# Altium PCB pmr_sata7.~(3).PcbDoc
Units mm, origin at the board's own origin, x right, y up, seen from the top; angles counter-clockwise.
Board outline 160 x 99.92 mm, 2 copper layers (Top Layer, Bottom Layer); 11 components, 38 nets, 173 pads, 16 vias.
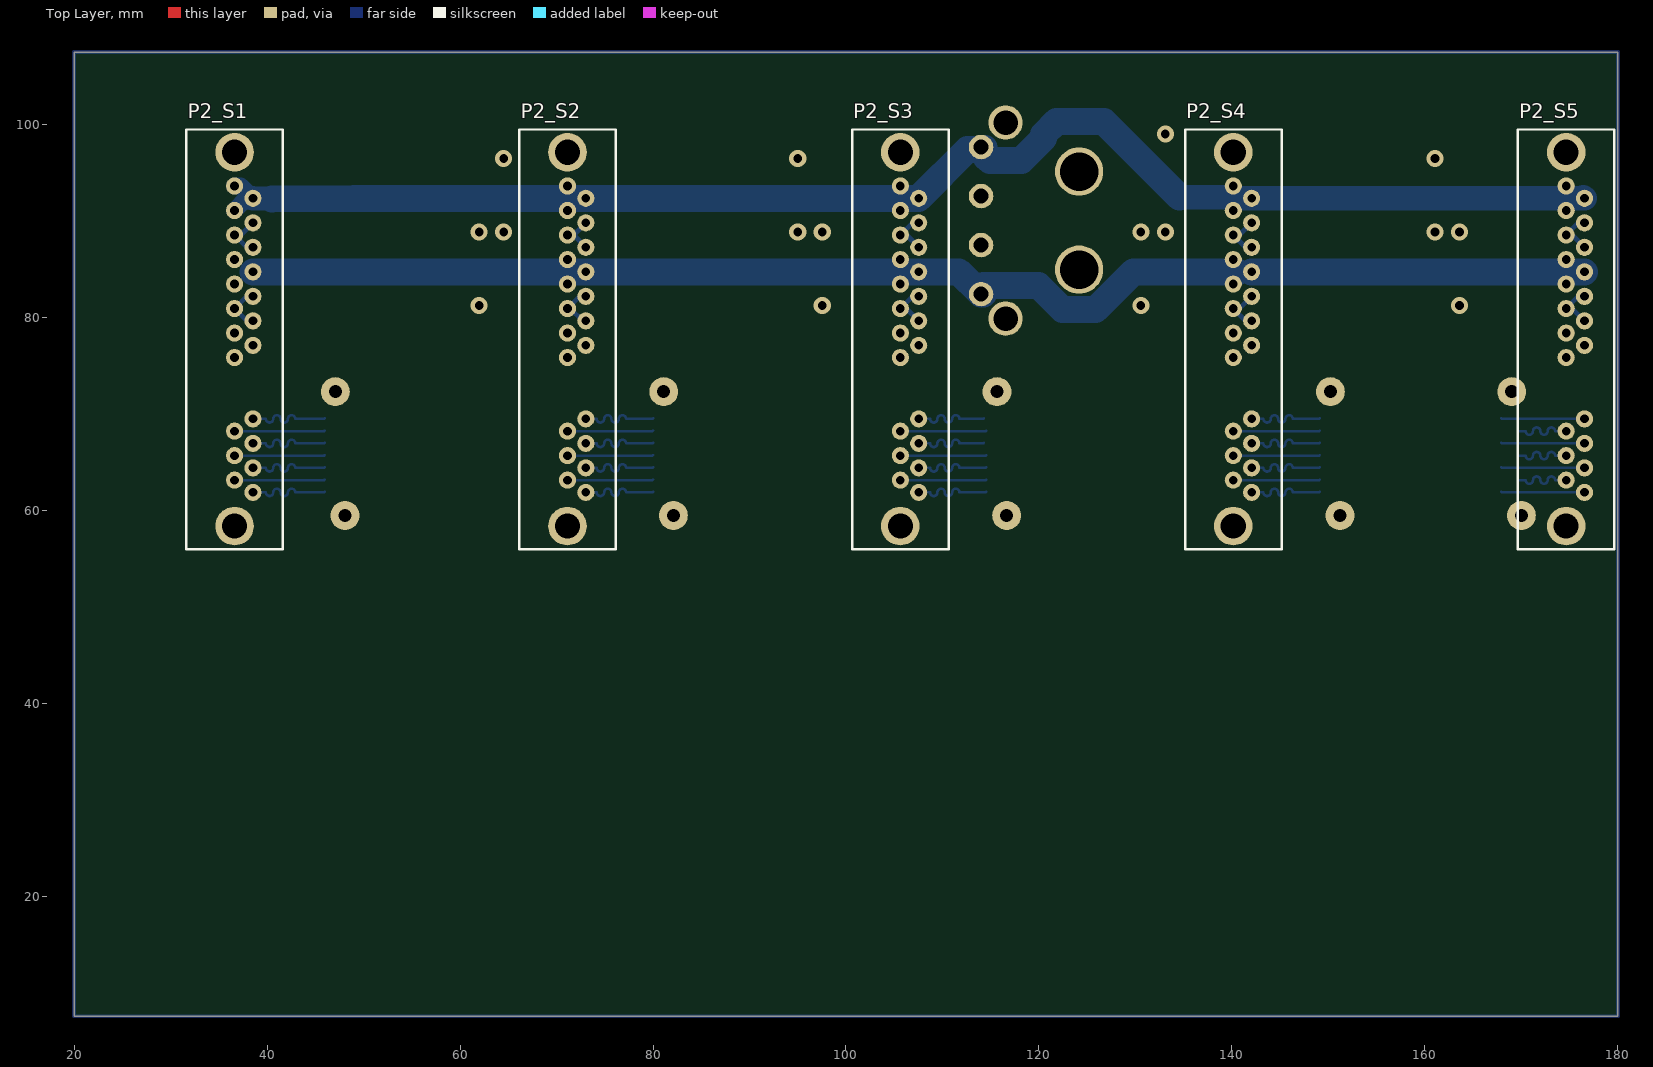
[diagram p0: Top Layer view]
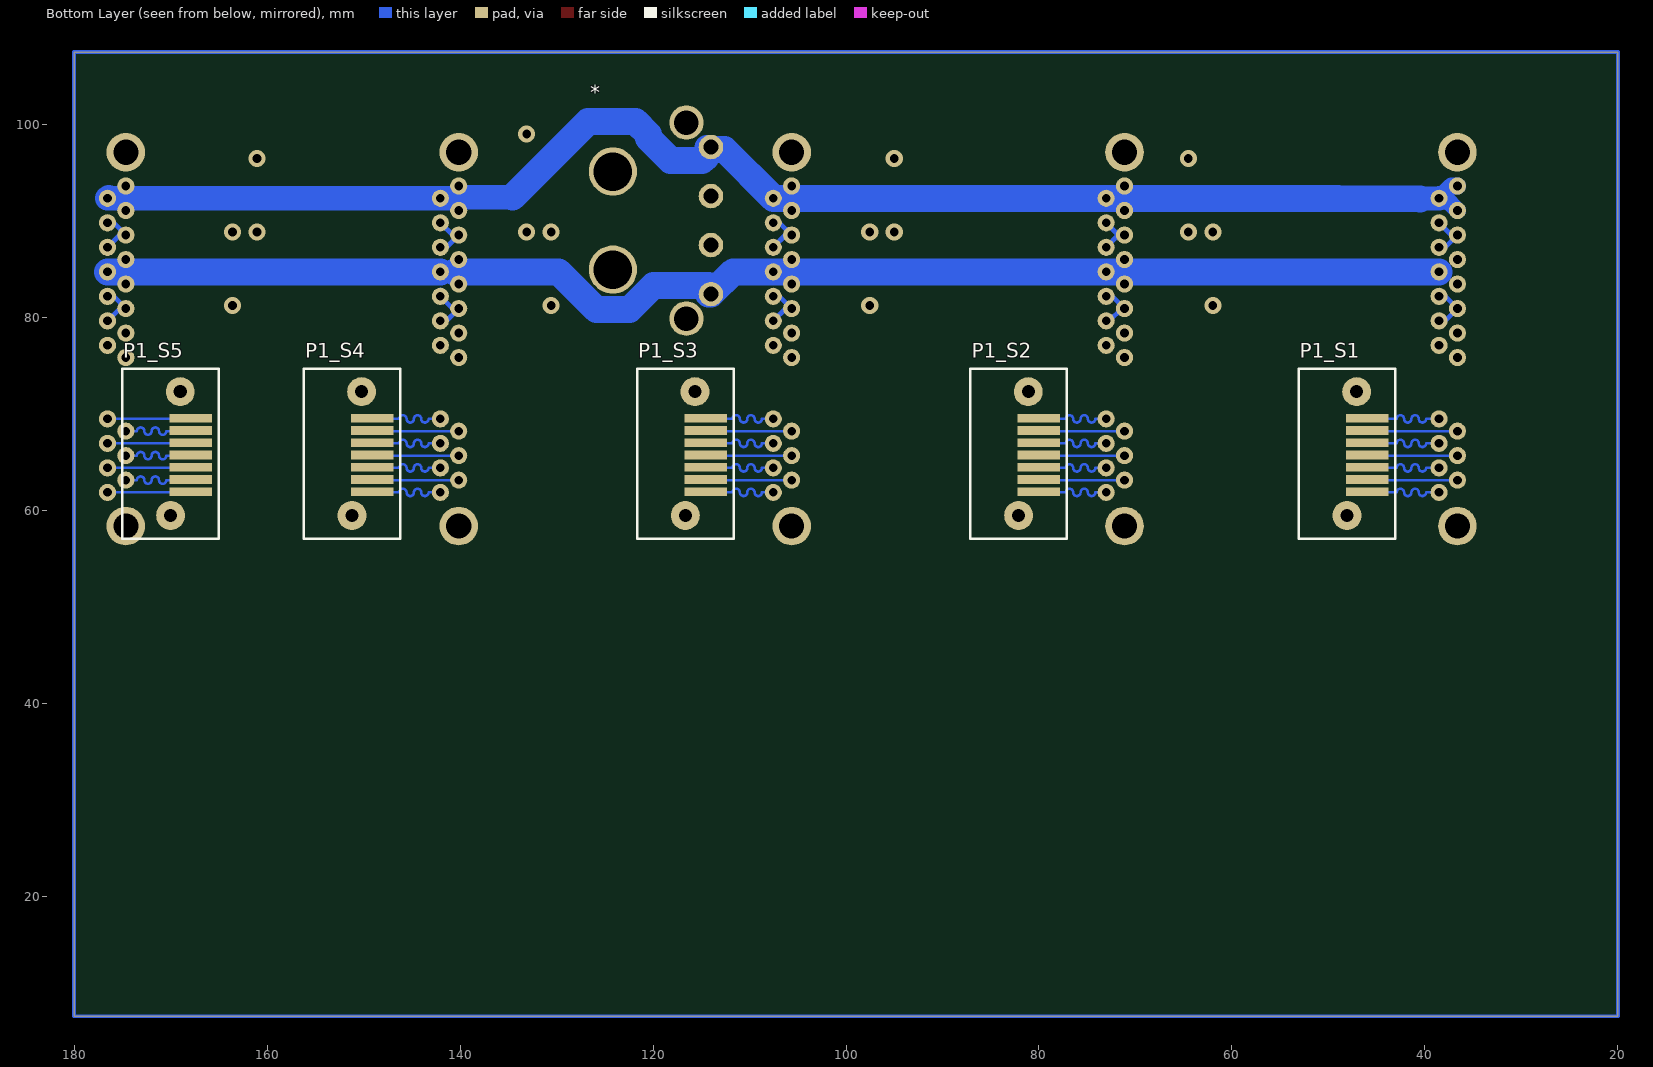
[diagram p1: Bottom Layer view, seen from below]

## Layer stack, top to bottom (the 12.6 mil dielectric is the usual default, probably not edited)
Top Solder: solder mask 0.0102, Solder Resist, Dk 3.5
Top Layer: signal copper 0.0356
Dielectric1: dielectric 0.32, FR-4, Dk 4.8
Bottom Layer: signal copper 0.0356
Bottom Solder: solder mask 0.0102, Solder Resist, Dk 3.5

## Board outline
20,7.62 20,107.544 180,107.544 180,7.62

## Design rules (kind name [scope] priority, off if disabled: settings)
Clearance [All] p1: gap=0.254
DiffPairsRouting [All] p1: maxlimit=0.254 minlimit=0.254 mostfreqgap=0.254 toplayer_minwidth=0.254 toplayer_maxwidth=0.381 toplayer_prefwidth=0.381 bottomlayer_minwidth=0.254 bottomlayer_maxwidth=0.381 bottomlayer_prefwidth=0.381 maxuncoupledlength=12.7
PolygonConnect [All] p1: connectstyle=Relief reliefconductorwidth=0.254 reliefentries=4 polygonreliefangle="90 Angle" airgapwidth=0.254
RoomDefinition top_level_sheet [InComponentClass('top_level_sheet')] p1 off: confinementstyle=ConfineIn formatcopy=TRUE lockcomponents=FALSE outline 180,10 197.5,10 197.5,37.5 180,37.5
RoomDefinition S5 [InComponentClass('S5')] p2 off: confinementstyle=ConfineIn formatcopy=TRUE lockcomponents=FALSE outline 29,122 53,122 53,170 29,170
RoomDefinition S3 [InComponentClass('S3')] p3 off: confinementstyle=ConfineIn formatcopy=TRUE lockcomponents=FALSE outline 76,114.83 100,114.83 100,162.83 76,162.83
RoomDefinition S2 [InComponentClass('S2')] p4 off: confinementstyle=ConfineIn formatcopy=TRUE lockcomponents=FALSE outline 108,115 132,115 132,163 108,163
RoomDefinition S1 [InComponentClass('S1')] p5 off: confinementstyle=ConfineIn formatcopy=TRUE lockcomponents=FALSE outline 127,116 151,116 151,164 127,164
RoomDefinition S4 [InComponentClass('S4')] p6 off: confinementstyle=ConfineIn formatcopy=TRUE lockcomponents=FALSE outline 192.278,29.464 184.912,29.464 184.912,40.386 192.278,40.386
RoutingVias [All] p1: holewidth=0.711 width=1.27 viastyle="Through Hole" minholewidth=0.711 minwidth=1.27 maxholewidth=0.711 maxwidth=1.27
SilkToSolderMaskClearance SilkscreenOverComponentPads [IsPad] p1: minsilkscreentomaskgap=0.254 clearancetoexposedcopper=TRUE
SolderMaskExpansion [All] p1: expansion=0.102
Width [All] p1: maxlimit=12.7 minlimit=0.254 preferedwidth=0.254
28 further rules are at their usual default settings.

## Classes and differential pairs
component class S1: P1_S1 P2_S1
component class S2: P1_S2 P2_S2
component class S3: P1_S3 P2_S3
component class S4: P1_S4 P2_S4
component class S5: P1_S5 P2_S5
channel class pmr_sata_single: S1 S2 S3 S4 S5
differential pair PAIR1_S1: +PAIR1_S1_P -PAIR1_S1_N
differential pair PAIR1_S2: +PAIR1_S2_P -PAIR1_S2_N
differential pair PAIR1_S3: +PAIR1_S3_P -PAIR1_S3_N
differential pair PAIR1_S4: +PAIR1_S4_P -PAIR1_S4_N
differential pair PAIR1_S5: +PAIR1_S5_P -PAIR1_S5_N
differential pair PAIR2_S1: +PAIR2_S1_P -PAIR2_S1_N
differential pair PAIR2_S2: +PAIR2_S2_P -PAIR2_S2_N
differential pair PAIR2_S3: +PAIR2_S3_P -PAIR2_S3_N
differential pair PAIR2_S4: +PAIR2_S4_P -PAIR2_S4_N
differential pair PAIR2_S5: +PAIR2_S5_P -PAIR2_S5_N

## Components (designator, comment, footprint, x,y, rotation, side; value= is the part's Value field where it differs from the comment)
* "PC_PWR_MOLEX" PC_PWR_MOLEX 124.156,90.08 r90 bottom
P1_S1 "SATA lille" "PMR_SATA -LILLE NY" 48.074,59.516 r270 bottom (schematic designator P1)
P1_S2 "SATA lille" "PMR_SATA -LILLE NY" 82.11,59.516 r270 bottom (schematic designator P1)
P1_S3 "SATA lille" "PMR_SATA -LILLE NY" 116.654,59.516 r270 bottom (schematic designator P1)
P1_S4 "SATA lille" "PMR_SATA -LILLE NY" 151.198,59.516 r270 bottom (schematic designator P1)
P1_S5 "SATA lille" "PMR_SATA -LILLE NY" 169.994,59.516 r270 bottom (schematic designator P1)
P2_S1 "SATA STOR" pmr_sata 36.636,58.42 r90 top (schematic designator P2)
P2_S2 "SATA STOR" pmr_sata 71.136,58.42 r90 top (schematic designator P2)
P2_S3 "SATA STOR" pmr_sata 105.636,58.42 r90 top (schematic designator P2)
P2_S4 "SATA STOR" pmr_sata 140.136,58.42 r90 top (schematic designator P2)
P2_S5 "SATA STOR" pmr_sata 174.636,58.42 r90 top (schematic designator P2)

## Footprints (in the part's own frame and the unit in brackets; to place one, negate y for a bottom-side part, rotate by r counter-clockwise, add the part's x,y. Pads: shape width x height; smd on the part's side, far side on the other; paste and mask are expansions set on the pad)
PC_PWR_MOLEX [mil]
  round 100 hole 60: 1(300,-400) 2(100,-400) 3(-100,-400) 4(-300,-400)
  round 140 hole 100: 5(400,-300) 6(-400,-300)
  round 196.85 hole 157.48: 7(-200,0) 8(200,0)
pmr_sata [mm]
  round 1.778 hole 0.9: P1(17.46,0) P2(18.73,-1.9) P3(20,0) P4(21.27,-1.9) P5(22.54,0) P6(23.81,-1.9) P7(25.08,0) P8(26.35,-1.9) P9(27.62,0) P10(28.89,-1.9) P11(30.16,0) P12(31.43,-1.9) P13(32.7,0) P14(33.97,-1.9) P15(35.24,0) S1(3.49,-1.9) S2(4.76,0) S3(6.03,-1.9) S4(7.3,0) S5(8.57,-1.9) S6(9.84,0) S7(11.11,-1.9)
  round 4 hole 2.6: S8(0,0) S8(38.74,0)
  silkscreen extent -2.4,-5 41.1,5
"PMR_SATA -LILLE NY" [mm]
  rect 0.9x4.4 smd: S1(-2.46,2.1) S2(-3.73,2.1) S3(-5,2.1) S4(-6.27,2.1) S5(-7.54,2.1) S6(-8.81,2.1) S7(-10.08,2.1)
  round 3 hole 1.35: S8(-12.83,1) S8(0,0)
  silkscreen extent -15.2,-5 2.4,5

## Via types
v1: diameter 1.778, hole 0.9, Top Layer to Bottom Layer, 16 vias

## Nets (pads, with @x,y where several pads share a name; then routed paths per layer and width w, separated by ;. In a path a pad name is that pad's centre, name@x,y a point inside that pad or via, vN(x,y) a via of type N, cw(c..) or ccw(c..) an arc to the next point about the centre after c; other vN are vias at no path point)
5V: *.4 P2_S1.P7 P2_S1.P8 P2_S1.P9 P2_S2.P7 P2_S2.P8 P2_S2.P9 P2_S3.P7 P2_S3.P8 P2_S3.P9 P2_S4.P7 P2_S4.P8 P2_S4.P9 P2_S5.P7 P2_S5.P8 P2_S5.P9 | length 141
  Bottom Layer w2.794: P2_S1.P8 P2_S2.P8 P2_S3.P8 111.686,84.77 *.4 114.227,82.46 114.227,83.349 119.937,83.349 122.437,80.849 125.875,80.849 129.796,84.77 140.556,84.77 ; P2_S4.P8 P2_S5.P8
12V: *.1 P2_S1.P13 P2_S1.P14 P2_S1.P15 P2_S2.P13 P2_S2.P14 P2_S2.P15 P2_S3.P13 P2_S3.P14 P2_S3.P15 P2_S4.P13 P2_S4.P14 P2_S4.P15 P2_S5.P13 P2_S5.P14 P2_S5.P15 | length 150.8
  Bottom Layer w1.778: P2_S1.P13 P2_S1.P14@37.906,92.39 ; P2_S1.P15 37.266,93.66 P2_S1.P14
  Bottom Layer w2.54: P2_S1.P14 40.513,92.329 ; *.1@113.752,97.456 *.1 114.406,97.7 *.1@114.406,96.52 ; 134.576,92.5 140.556,92.5 140.666,92.39 P2_S4.P14 P2_S5.P14 P2_S5.P14@176.426,92.5
  Bottom Layer w2.794: 40.513,92.329 49.022,92.373 65.532,92.373 65.549,92.39 P2_S2.P14 74.088,92.39 74.105,92.373 88.646,92.373 88.663,92.39 P2_S3.P14 112.602,97.456 *.1@113.752,97.456 ; 114.688,96.52 114.905,96.303 118.167,96.303 120.473,98.609 120.473,99.01 121.793,100.33 126.746,100.33 134.576,92.5
GND: P2_S1.P4 P2_S1.P5 P2_S1.P6 P2_S1.P10 P2_S1.P11 P2_S1.P12 P2_S2.P4 P2_S2.P5 P2_S2.P6 P2_S2.P10 P2_S2.P11 P2_S2.P12 P2_S3.P4 P2_S3.P5 P2_S3.P6 P2_S3.P10 P2_S3.P11 P2_S3.P12 P2_S4.P4 P2_S4.P5 P2_S4.P6 P2_S4.P10 P2_S4.P11 P2_S4.P12 P2_S5.P4 P2_S5.P5 P2_S5.P6 P2_S5.P10 P2_S5.P11 P2_S5.P12 | length 49.2
  Bottom Layer w0.508: P2_S1.P4 37.906,79.69 P2_S1.P5 37.906,82.23 P2_S1.P6 ; P2_S1.P10 37.906,87.31 P2_S1.P11 37.266,88.58 P2_S1.P12 ; P2_S2.P11 P2_S2.P11@71.766,88.58 ; P2_S2.P4 72.71,79.69 71.44,80.96 P2_S2.P5 72.406,82.23 P2_S2.P6 ; P2_S2.P10@73.036,86.675 P2_S2.P10 P2_S2.P11@71.766,88.58 ; P2_S2.P12 P2_S2.P11@71.766,88.58 ; P2_S3.P4 106.266,80.96 P2_S3.P5 106.906,82.23 P2_S3.P6 ; P2_S3.P10 106.266,88.58 P2_S3.P11 106.906,89.85 P2_S3.P12 ; P2_S4.P4 141.406,79.69 P2_S4.P5 140.766,80.96 P2_S4.P6 P2_S4.P6@142.036,82.865 ; P2_S4.P10 141.406,87.31 P2_S4.P11 140.766,88.58 P2_S4.P12 ; P2_S5.P4 175.266,80.96 P2_S5.P5 175.906,82.23 P2_S5.P6 ; P2_S5.P10 175.266,88.58 P2_S5.P11 175.906,89.85 P2_S5.P12
  other v1: 61.976,81.28 97.536,81.28 130.556,81.28 163.576,81.28 61.976,88.9 64.516,88.9 94.996,88.9 97.536,88.9 130.556,88.9 133.096,88.9 161.036,88.9 163.576,88.9 64.516,96.52 94.996,96.52 161.036,96.52 133.096,99.06
NetP1_S1_S1: P1_S1.S1 P2_S1.S1 | length 8.6
  Bottom Layer w0.254: P2_S1.S1@39.116,61.91 39.878,61.91 ccw(c40.259,61.91) 40.64,61.91 cw(c41.021,61.91) 41.402,61.91 ccw(c41.783,61.91) 42.164,61.91 cw(c42.545,61.91) 42.926,61.91 45.908,61.91 P1_S1.S1
NetP1_S1_S4: P1_S1.S4 P2_S1.S4 | length 9.4
  Bottom Layer w0.254: P2_S1.S4 45.908,65.72 P1_S1.S4
NetP1_S1_S7: P1_S1.S7 P2_S1.S7 | length 9.2
  Bottom Layer w0.254: P2_S1.S7 39.878,69.53 ccw(c40.259,69.53) 40.64,69.53 cw(c41.021,69.53) 41.402,69.53 ccw(c41.783,69.53) 42.164,69.53 cw(c42.545,69.53) 42.926,69.53 45.908,69.53 P1_S1.S7
NetP1_S2_S1: P1_S2.S1 P2_S2.S1 | length 8.4
  Bottom Layer w0.254: P2_S2.S1@73.406,61.91 74.168,61.91 ccw(c74.549,61.91) 74.93,61.91 cw(c75.311,61.91) 75.692,61.91 ccw(c76.073,61.91) 76.454,61.91 cw(c76.835,61.91) 77.216,61.91 79.944,61.91 P1_S2.S1
NetP1_S2_S4: P1_S2.S4 P2_S2.S4 | length 8.9
  Bottom Layer w0.254: P2_S2.S4 79.944,65.72 P1_S2.S4
NetP1_S2_S7: P1_S2.S7 P2_S2.S7 | length 8.4
  Bottom Layer w0.254: P2_S2.S7@73.406,69.53 74.168,69.53 ccw(c74.549,69.53) 74.93,69.53 cw(c75.311,69.53) 75.692,69.53 ccw(c76.073,69.53) 76.454,69.53 cw(c76.835,69.53) 77.216,69.53 79.944,69.53 P1_S2.S7
NetP1_S3_S1: P1_S3.S1 P2_S3.S1 | length 8.4
  Bottom Layer w0.254: P2_S3.S1@107.95,61.91 108.712,61.91 ccw(c109.093,61.91) 109.474,61.91 cw(c109.855,61.91) 110.236,61.91 ccw(c110.617,61.91) 110.998,61.91 cw(c111.379,61.91) 111.76,61.91 114.488,61.91 P1_S3.S1
NetP1_S3_S4: P1_S3.S4 P2_S3.S4 | length 8.9
  Bottom Layer w0.254: P2_S3.S4 114.488,65.72 P1_S3.S4
NetP1_S3_S7: P1_S3.S7 P2_S3.S7 | length 8.1
  Bottom Layer w0.254: P2_S3.S7@107.95,69.53 108.712,69.53 ccw(c109.093,69.53) 109.474,69.53 cw(c109.855,69.53) 110.236,69.53 ccw(c110.617,69.53) 110.998,69.53 cw(c111.379,69.53) 111.76,69.53 114.234,69.53 P1_S3.S7@114.3,69.596
NetP1_S4_S1: P1_S4.S1 P2_S4.S1 | length 8.4
  Bottom Layer w0.254: P2_S4.S1@142.494,61.91 143.256,61.91 ccw(c143.637,61.91) 144.018,61.91 cw(c144.399,61.91) 144.78,61.91 ccw(c145.161,61.91) 145.542,61.91 cw(c145.923,61.91) 146.304,61.91 149.032,61.91 P1_S4.S1
NetP1_S4_S4: P1_S4.S4 P2_S4.S4 | length 9
  Bottom Layer w0.254: P2_S4.S4 149.032,65.72 P1_S4.S4
NetP1_S4_S7: P1_S4.S7 P2_S4.S7 | length 8.4
  Bottom Layer w0.254: P2_S4.S7@142.494,69.53 143.256,69.53 ccw(c143.637,69.53) 144.018,69.53 cw(c144.399,69.53) 144.78,69.53 ccw(c145.161,69.53) 145.542,69.53 cw(c145.923,69.53) 146.304,69.53 149.032,69.53 P1_S4.S7
NetP1_S5_S1: P1_S5.S1 P2_S5.S1 | length 8.7
  Bottom Layer w0.254: P1_S5.S1 167.96,61.91 P2_S5.S1
NetP1_S5_S4: P1_S5.S4 P2_S5.S4 | length 5.8
  Bottom Layer w0.254: P1_S5.S4@169.672,65.72 170.434,65.72 ccw(c170.815,65.72) 171.196,65.72 cw(c171.577,65.72) 171.958,65.72 ccw(c172.339,65.72) 172.72,65.72 cw(c173.101,65.72) 173.482,65.72 173.702,65.72
NetP1_S5_S7: P1_S5.S7 P2_S5.S7 | length 8.7
  Bottom Layer w0.254: P1_S5.S7 167.96,69.53 P2_S5.S7
PAIR1_S1_N: P1_S1.S2 P2_S1.S2 | length 9.4
  Bottom Layer w0.254: P2_S1.S2 45.908,63.18 P1_S1.S2
PAIR1_S1_P: P1_S1.S3 P2_S1.S3 | length 8.6
  Bottom Layer w0.254: P2_S1.S3@39.116,64.45 39.878,64.45 ccw(c40.259,64.45) 40.64,64.45 cw(c41.021,64.45) 41.402,64.45 ccw(c41.783,64.45) 42.164,64.45 cw(c42.545,64.45) 42.926,64.45 45.908,64.45 P1_S1.S3
PAIR1_S2_N: P1_S2.S2 P2_S2.S2 | length 8.9
  Bottom Layer w0.254: P2_S2.S2 79.944,63.18 P1_S2.S2
PAIR1_S2_P: P1_S2.S3 P2_S2.S3 | length 8.4
  Bottom Layer w0.254: P2_S2.S3@73.406,64.45 74.168,64.45 ccw(c74.549,64.45) 74.93,64.45 cw(c75.311,64.45) 75.692,64.45 ccw(c76.073,64.45) 76.454,64.45 cw(c76.835,64.45) 77.216,64.45 79.944,64.45 P1_S2.S3
PAIR1_S3_N: P1_S3.S2 P2_S3.S2 | length 8.9
  Bottom Layer w0.254: P2_S3.S2 114.488,63.18 P1_S3.S2
PAIR1_S3_P: P1_S3.S3 P2_S3.S3 | length 8.4
  Bottom Layer w0.254: P2_S3.S3@107.95,64.45 108.712,64.45 ccw(c109.093,64.45) 109.474,64.45 cw(c109.855,64.45) 110.236,64.45 ccw(c110.617,64.45) 110.998,64.45 cw(c111.379,64.45) 111.76,64.45 114.488,64.45 P1_S3.S3
PAIR1_S4_N: P1_S4.S2 P2_S4.S2 | length 9.3
  Bottom Layer w0.254: P2_S4.S2 140.136,63.428 140.384,63.18 149.032,63.18 P1_S4.S2
PAIR1_S4_P: P1_S4.S3 P2_S4.S3 | length 8.4
  Bottom Layer w0.254: P2_S4.S3@142.494,64.45 143.256,64.45 ccw(c143.637,64.45) 144.018,64.45 cw(c144.399,64.45) 144.78,64.45 ccw(c145.161,64.45) 145.542,64.45 cw(c145.923,64.45) 146.304,64.45 149.032,64.45 P1_S4.S3
PAIR1_S5_N: P1_S5.S2 P2_S5.S2 | length 5.8
  Bottom Layer w0.254: P1_S5.S2@169.672,63.18 170.434,63.18 ccw(c170.815,63.18) 171.196,63.18 cw(c171.577,63.18) 171.958,63.18 ccw(c172.339,63.18) 172.72,63.18 cw(c173.101,63.18) 173.482,63.18 173.702,63.18
PAIR1_S5_P: P1_S5.S3 P2_S5.S3 | length 8.7
  Bottom Layer w0.254: P1_S5.S3 167.96,64.45 P2_S5.S3
PAIR2_S1_N: P1_S1.S5 P2_S1.S5 | length 9.2
  Bottom Layer w0.254: P2_S1.S5 39.878,66.99 ccw(c40.259,66.99) 40.64,66.99 cw(c41.021,66.99) 41.402,66.99 ccw(c41.783,66.99) 42.164,66.99 cw(c42.545,66.99) 42.926,66.99 45.908,66.99 P1_S1.S5
PAIR2_S1_P: P1_S1.S6 P2_S1.S6 | length 9.4
  Bottom Layer w0.254: P2_S1.S6 45.908,68.26 P1_S1.S6
PAIR2_S2_N: P1_S2.S5 P2_S2.S5 | length 8.4
  Bottom Layer w0.254: P2_S2.S5@73.406,66.99 74.168,66.99 ccw(c74.549,66.99) 74.93,66.99 cw(c75.311,66.99) 75.692,66.99 ccw(c76.073,66.99) 76.454,66.99 cw(c76.835,66.99) 77.216,66.99 79.944,66.99 P1_S2.S5
PAIR2_S2_P: P1_S2.S6 P2_S2.S6 | length 8.9
  Bottom Layer w0.254: P2_S2.S6 79.944,68.26 P1_S2.S6
PAIR2_S3_N: P1_S3.S5 P2_S3.S5 | length 8.1
  Bottom Layer w0.254: P2_S3.S5@107.95,66.99 108.712,66.99 ccw(c109.093,66.99) 109.474,66.99 cw(c109.855,66.99) 110.236,66.99 ccw(c110.617,66.99) 110.998,66.99 cw(c111.379,66.99) 111.76,66.99 114.234,66.99 P1_S3.S5@114.3,67.056
PAIR2_S3_P: P1_S3.S6 P2_S3.S6 | length 8.9
  Bottom Layer w0.254: P2_S3.S6 114.488,68.26 P1_S3.S6
PAIR2_S4_N: P1_S4.S5 P2_S4.S5 | length 8.4
  Bottom Layer w0.254: P2_S4.S5@142.494,66.99 143.256,66.99 ccw(c143.637,66.99) 144.018,66.99 cw(c144.399,66.99) 144.78,66.99 ccw(c145.161,66.99) 145.542,66.99 cw(c145.923,66.99) 146.304,66.99 149.032,66.99 P1_S4.S5
PAIR2_S4_P: P1_S4.S6 P2_S4.S6 | length 9
  Bottom Layer w0.254: P2_S4.S6 149.032,68.26 P1_S4.S6
PAIR2_S5_N: P1_S5.S5 P2_S5.S5 | length 8.7
  Bottom Layer w0.254: P1_S5.S5 167.96,66.99 P2_S5.S5
PAIR2_S5_P: P1_S5.S6 P2_S5.S6 | length 5.8
  Bottom Layer w0.254: P1_S5.S6@169.672,68.26 170.434,68.26 ccw(c170.815,68.26) 171.196,68.26 cw(c171.577,68.26) 171.958,68.26 ccw(c172.339,68.26) 172.72,68.26 cw(c173.101,68.26) 173.482,68.26 173.702,68.26
pads on no net: *.2 *.3 *.5 *.6 *.7 *.8 P1_S1.S8 P1_S2.S8 P1_S3.S8 P1_S4.S8 P1_S5.S8 P2_S1.P1 P2_S1.P2 P2_S1.P3 P2_S1.S8 P2_S2.P1 P2_S2.P2 P2_S2.P3 P2_S2.S8 P2_S3.P1 P2_S3.P2 P2_S3.P3 P2_S3.S8 P2_S4.P1 P2_S4.P2 P2_S4.P3 P2_S4.S8 P2_S5.P1 P2_S5.P2 P2_S5.P3 P2_S5.S8
copper on no net: | length 519.8
  Bottom Layer w0.381: 20,7.62 20,107.544 180,107.544 180,7.62 20,7.62

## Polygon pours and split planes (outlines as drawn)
GND on Bottom Layer "BOT GND" (solid, shelved, pour order 0): 20,7.62 20,107.544 180,107.544 180,7.62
